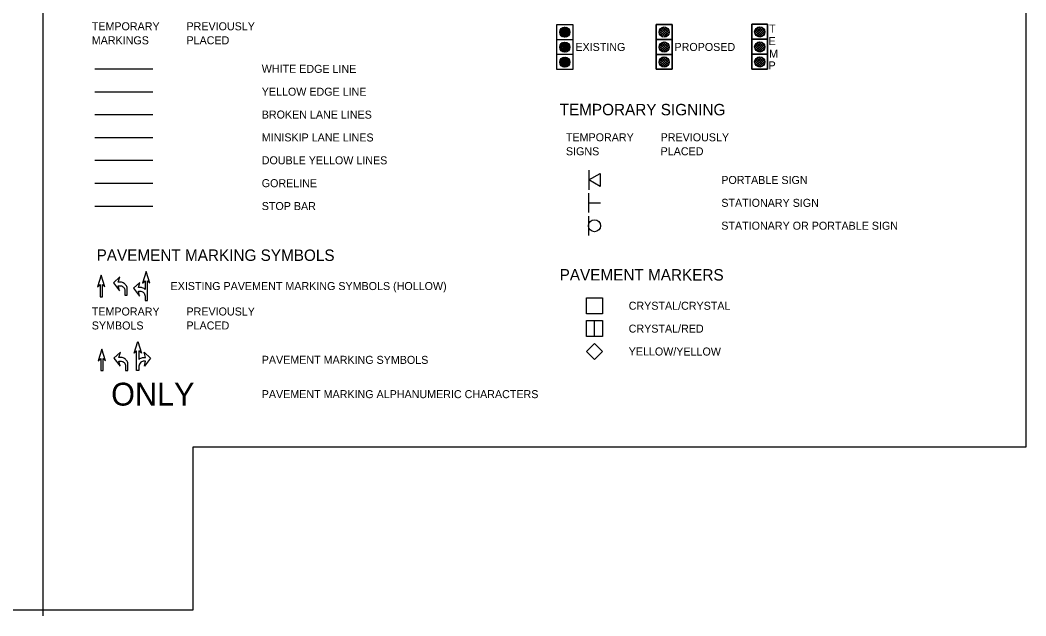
# Model space of a CAD drawing. Extents: x 2486454 to 2490507, y 369321 to 372999.
# Drawn here: x 2487627 to 2488507, y 370213 to 370734 of the extents above; entities that cross this region are included whole.
import ezdxf

# ---------------------------------------------------------------- set-up
doc = ezdxf.new("R2010")
doc.units = 0
for name, color, linetype in [('Exist Mkg Solid White Crosswalks', 7, 'Continuous'), ('MARK CRYSTAL CRYSTAL RPM CELL', 7, 'Continuous'), ('MARK CRYSTAL RED RPM CELL', 7, 'Continuous'), ('MARK YELLOW RPM CELL', 7, 'Continuous'), ('TC DEV SIGN', 7, 'Continuous'), ('TC DEV SIGNAL', 7, 'Continuous'), ('TC PM CENTER DOUBLE 6 Y', 7, 'Continuous'), ('TC PM CHARACTER', 7, 'Continuous'), ('TC PM EDGELINE 6 W P6', 7, 'Continuous'), ('TC PM EDGELINE 6 Y P7', 7, 'Continuous'), ('TC PM GORELINE 12 W PS', 7, 'Continuous'), ('TC PM MINISKIP 3-9 6 W PK', 7, 'Continuous'), ('TC PM SKIP 6 W PJ', 7, 'Continuous'), ('TC PM STOP BAR 24 W P2', 7, 'Continuous'), ('TC PM SYMBOL', 7, 'Continuous'), ('TC SHEET BORDER LINE THIN', 7, 'Continuous'), ('TC SHEET LAYOUT SHAPE', 7, 'Continuous'), ('TC SHEET TEXT', 7, 'Continuous')]:
    doc.layers.add(name, color=color, linetype=linetype)

msp = doc.modelspace()

# ---------------------------------------------------------------- linework, layer by layer
at = {"layer": 'Exist Mkg Solid White Crosswalks'}
for points in [[(2487695.06, 370500.97), (2487697.23, 370502.97), (2487697.23, 370492.3), (2487699.23, 370492.3), (2487699.23, 370502.97), (2487701.39, 370500.97), (2487698.22, 370511.13)], [(2487718.95, 370493.72), (2487720.95, 370493.72), (2487720.94, 370498.88), (2487720.89, 370499.84), (2487720.76, 370500.56), (2487720.51, 370501.35), (2487720.16, 370502.01), (2487719.82, 370502.52), (2487719.25, 370503.18), (2487718.75, 370503.62), (2487718.15, 370504.09), (2487717.36, 370504.56), (2487716.73, 370504.81), (2487715.88, 370505.06), (2487714.71, 370505.22), (2487713.11, 370505.22), (2487714.44, 370509.71), (2487708.77, 370504.54), (2487714.11, 370497.55), (2487713.11, 370502.05), (2487714.44, 370502.05), (2487715.19, 370502.01), (2487715.88, 370501.82), (2487716.42, 370501.57), (2487717.11, 370501.16), (2487717.58, 370500.78), (2487718.12, 370500.12), (2487718.5, 370499.37), (2487718.78, 370498.61), (2487718.94, 370497.55)], [(2487738.59, 370488.97), (2487738.58, 370506.3), (2487740.74, 370504.3), (2487737.57, 370514.47), (2487734.41, 370504.3), (2487736.58, 370506.3), (2487736.58, 370498.76), (2487735.66, 370499.48), (2487734.96, 370499.9), (2487734.06, 370500.22), (2487733.33, 370500.38), (2487732.4, 370500.51), (2487730.75, 370500.46), (2487732.08, 370504.96), (2487726.41, 370499.79), (2487731.75, 370492.8), (2487730.75, 370497.3), (2487732.05, 370497.27), (2487732.81, 370497.24), (2487733.58, 370497.05), (2487734.26, 370496.7), (2487734.93, 370496.31), (2487735.6, 370495.61), (2487736.12, 370494.74), (2487736.44, 370493.82), (2487736.6, 370492.76), (2487736.59, 370488.97)]]:
    msp.add_lwpolyline(points, close=True, dxfattribs=at)
at = {"layer": 'MARK CRYSTAL CRYSTAL RPM CELL'}
msp.add_lwpolyline([(2488122.41, 370491.49), (2488136.41, 370491.48), (2488136.41, 370477.49), (2488122.41, 370477.49), (2488122.41, 370491.49)], dxfattribs=at)
at = {"layer": 'MARK CRYSTAL RED RPM CELL'}
msp.add_lwpolyline([(2488122.41, 370471.49), (2488136.41, 370471.48), (2488136.41, 370457.49), (2488122.41, 370457.49), (2488122.41, 370471.49)], dxfattribs=at)
for points in [[(2488129.41, 370471.49), (2488136.41, 370471.48), (2488136.41, 370457.49), (2488129.4, 370457.49)], [(2488129.41, 370437.49), (2488136.41, 370444.48), (2488129.41, 370451.48), (2488122.41, 370444.48)]]:
    msp.add_lwpolyline(points, close=True, dxfattribs=at)
at = {"layer": 'MARK YELLOW RPM CELL'}
msp.add_lwpolyline([(2488129.41, 370437.49), (2488136.41, 370444.48), (2488129.41, 370451.48), (2488122.41, 370444.48)], close=True, dxfattribs=at)
at = {"layer": 'TC DEV SIGN'}
for p, q in [((2488124.51, 370602.98), (2488124.51, 370586)), ((2488124.51, 370594.49), (2488134.31, 370600.11)), ((2488134.31, 370588.86), (2488124.51, 370594.49)), ((2488134.31, 370600.11), (2488134.31, 370588.86)), ((2488124.15, 370582.98), (2488124.15, 370566)), ((2488124.15, 370574.49), (2488134.67, 370574.49)), ((2488124.15, 370562.98), (2488124.15, 370546))]:
    msp.add_line(p, q, dxfattribs=at)
msp.add_circle((2488129.41, 370554.49), 5.26, dxfattribs=at)
at = {"layer": 'TC DEV SIGNAL'}
for p, q in [((2488096.55, 370730.38), (2488110.35, 370730.38)), ((2488096.55, 370717.28), (2488096.55, 370730.38)), ((2488099.03, 370724), (2488103.14, 370728.11)), ((2488099.13, 370722.69), (2488104.45, 370728.01)), ((2488099.51, 370721.65), (2488105.48, 370727.63)), ((2488099.77, 370726.16), (2488100.98, 370727.37)), ((2488100.07, 370720.81), (2488106.33, 370727.06)), ((2488100.13, 370726.63), (2488106.4, 370720.36)), ((2488100.81, 370720.12), (2488107.01, 370726.33)), ((2488100.88, 370727.3), (2488107.07, 370721.11)), ((2488101.79, 370727.8), (2488107.57, 370722.02)), ((2488102.92, 370728.09), (2488107.86, 370723.15)), ((2488104.4, 370728.02), (2488107.79, 370724.63)), ((2488110.35, 370730.38), (2488110.35, 370717.28)), ((2488185.92, 370723.96), (2488190.22, 370728.26)), ((2488186.27, 370722.16), (2488192.02, 370727.96)), ((2488192.92, 370720.31), (2488186.77, 370726.41)), ((2488187.07, 370720.86), (2488193.32, 370727.11)), ((2488193.97, 370721.36), (2488187.82, 370727.51)), ((2488194.62, 370722.81), (2488189.27, 370728.16)), ((2488194.57, 370724.96), (2488191.47, 370728.11)), ((2488269.49, 370724.02), (2488273.79, 370728.32)), ((2488269.84, 370722.22), (2488275.59, 370728.02)), ((2488276.49, 370720.37), (2488270.34, 370726.47)), ((2488270.64, 370720.92), (2488276.89, 370727.17)), ((2488277.54, 370721.42), (2488271.39, 370727.57)), ((2488278.19, 370722.87), (2488272.84, 370728.22)), ((2488278.14, 370725.02), (2488275.04, 370728.17)), ((2488099.02, 370723.5), (2488103.27, 370719.25)), ((2488099.15, 370724.78), (2488104.55, 370719.38)), ((2488099.55, 370725.8), (2488105.57, 370719.78)), ((2488099.57, 370721.53), (2488101.3, 370719.8)), ((2488101.7, 370719.61), (2488107.53, 370725.43)), ((2488102.81, 370719.29), (2488107.84, 370724.33)), ((2488104.24, 370719.32), (2488107.82, 370722.89)), ((2488189.42, 370719.51), (2488186.02, 370722.96)), ((2488191.47, 370719.61), (2488186.07, 370725.01)), ((2488188.27, 370719.96), (2488194.22, 370725.86)), ((2488189.92, 370719.51), (2488194.72, 370724.26)), ((2488192.82, 370720.26), (2488194.07, 370721.51)), ((2488272.99, 370719.57), (2488269.59, 370723.02)), ((2488275.04, 370719.67), (2488269.64, 370725.07)), ((2488271.84, 370720.02), (2488277.79, 370725.92)), ((2488273.49, 370719.57), (2488278.29, 370724.32)), ((2488276.39, 370720.32), (2488277.64, 370721.57)), ((2488096.55, 370717.28), (2488110.35, 370717.28)), ((2488096.55, 370704.18), (2488096.55, 370717.28)), ((2488099.02, 370710.63), (2488103.41, 370715.02)), ((2488099.02, 370710.72), (2488103.59, 370706.15)), ((2488099.18, 370709.38), (2488104.66, 370714.85)), ((2488099.22, 370711.93), (2488104.8, 370706.36)), ((2488099.3, 370709.03), (2488101.9, 370706.43)), ((2488099.43, 370712.45), (2488101.58, 370714.61)), ((2488099.6, 370708.38), (2488105.65, 370714.44)), ((2488099.67, 370712.9), (2488105.77, 370706.8)), ((2488100.2, 370707.57), (2488106.47, 370713.84)), ((2488100.29, 370713.7), (2488106.56, 370707.42)), ((2488100.96, 370706.91), (2488107.12, 370713.08)), ((2488101.07, 370714.33), (2488107.2, 370708.2)), ((2488101.89, 370706.43), (2488107.61, 370712.15)), ((2488102.03, 370714.79), (2488107.65, 370709.16)), ((2488103.04, 370706.17), (2488107.87, 370711)), ((2488103.21, 370715.02), (2488107.88, 370710.34)), ((2488104.58, 370706.29), (2488107.74, 370709.46)), ((2488104.84, 370714.8), (2488107.67, 370711.97)), ((2488110.35, 370717.28), (2488110.35, 370704.18)), ((2488185.92, 370710.86), (2488190.22, 370715.16)), ((2488189.42, 370706.41), (2488186.02, 370709.86)), ((2488191.47, 370706.51), (2488186.07, 370711.91)), ((2488186.27, 370709.06), (2488192.02, 370714.86)), ((2488192.92, 370707.21), (2488186.77, 370713.31)), ((2488187.07, 370707.76), (2488193.32, 370714.01)), ((2488193.97, 370708.26), (2488187.82, 370714.41)), ((2488188.27, 370706.86), (2488194.22, 370712.76)), ((2488194.62, 370709.71), (2488189.27, 370715.06)), ((2488189.92, 370706.41), (2488194.72, 370711.16)), ((2488194.57, 370711.86), (2488191.47, 370715.01)), ((2488269.49, 370710.92), (2488273.79, 370715.22)), ((2488272.99, 370706.47), (2488269.59, 370709.92)), ((2488275.04, 370706.57), (2488269.64, 370711.97)), ((2488269.84, 370709.12), (2488275.59, 370714.92)), ((2488276.49, 370707.27), (2488270.34, 370713.37)), ((2488270.64, 370707.82), (2488276.89, 370714.07)), ((2488277.54, 370708.32), (2488271.39, 370714.47)), ((2488271.84, 370706.92), (2488277.79, 370712.82)), ((2488278.19, 370709.77), (2488272.84, 370715.12)), ((2488273.49, 370706.47), (2488278.29, 370711.22)), ((2488278.14, 370711.92), (2488275.04, 370715.07)), ((2488110.35, 370704.18), (2488096.55, 370704.18)), ((2488096.55, 370691.08), (2488096.55, 370704.18)), ((2488099.04, 370697.99), (2488102.95, 370701.89)), ((2488099.1, 370696.63), (2488104.31, 370701.84)), ((2488099.45, 370695.57), (2488105.37, 370701.49)), ((2488099.75, 370699.93), (2488105.9, 370693.78)), ((2488100, 370694.7), (2488106.24, 370700.94)), ((2488100.39, 370700.7), (2488106.67, 370694.43)), ((2488100.71, 370694), (2488106.94, 370700.23)), ((2488101.2, 370701.31), (2488107.28, 370695.23)), ((2488102.19, 370701.74), (2488107.71, 370696.22)), ((2488103.41, 370701.92), (2488107.89, 370697.45)), ((2488105.18, 370701.57), (2488107.54, 370699.21)), ((2488110.35, 370704.18), (2488110.35, 370691.08)), ((2488185.92, 370697.76), (2488190.22, 370702.06)), ((2488186.27, 370695.96), (2488192.02, 370701.76)), ((2488192.92, 370694.11), (2488186.77, 370700.21)), ((2488187.07, 370694.66), (2488193.32, 370700.91)), ((2488193.97, 370695.16), (2488187.82, 370701.31)), ((2488194.62, 370696.61), (2488189.27, 370701.96)), ((2488194.57, 370698.76), (2488191.47, 370701.91)), ((2488192.82, 370707.16), (2488194.07, 370708.41)), ((2488269.49, 370697.82), (2488273.79, 370702.12)), ((2488269.84, 370696.02), (2488275.59, 370701.82)), ((2488276.49, 370694.17), (2488270.34, 370700.27)), ((2488270.64, 370694.72), (2488276.89, 370700.97)), ((2488277.54, 370695.22), (2488271.39, 370701.37)), ((2488278.19, 370696.67), (2488272.84, 370702.02)), ((2488278.14, 370698.82), (2488275.04, 370701.97)), ((2488276.39, 370707.22), (2488277.64, 370708.47)), ((2488099.03, 370697.82), (2488103.79, 370693.06)), ((2488099.19, 370696.25), (2488102.21, 370693.22)), ((2488099.28, 370698.99), (2488104.96, 370693.31)), ((2488101.59, 370693.46), (2488107.48, 370699.35)), ((2488102.66, 370693.12), (2488107.82, 370698.28)), ((2488104.04, 370693.09), (2488107.85, 370696.89)), ((2488189.42, 370693.31), (2488186.02, 370696.76)), ((2488191.47, 370693.41), (2488186.07, 370698.81)), ((2488188.27, 370693.76), (2488194.22, 370699.66)), ((2488189.92, 370693.31), (2488194.72, 370698.06)), ((2488192.82, 370694.06), (2488194.07, 370695.31)), ((2488272.99, 370693.37), (2488269.59, 370696.82)), ((2488275.04, 370693.47), (2488269.64, 370698.87)), ((2488271.84, 370693.82), (2488277.79, 370699.72)), ((2488273.49, 370693.37), (2488278.29, 370698.12)), ((2488276.39, 370694.12), (2488277.64, 370695.37)), ((2488110.35, 370691.08), (2488096.55, 370691.08))]:
    msp.add_line(p, q, dxfattribs=at)
for points in [[(2488183.42, 370730.56), (2488197.22, 370730.56), (2488197.22, 370691.26), (2488183.42, 370691.26)], [(2488183.42, 370717.46), (2488197.22, 370717.46), (2488197.22, 370730.56), (2488183.42, 370730.56)], [(2488266.99, 370730.62), (2488280.79, 370730.62), (2488280.79, 370691.32), (2488266.99, 370691.32)], [(2488266.99, 370717.52), (2488280.79, 370717.52), (2488280.79, 370730.62), (2488266.99, 370730.62)], [(2488266.99, 370704.42), (2488280.79, 370704.42), (2488280.79, 370717.52), (2488266.99, 370717.52)], [(2488183.42, 370704.36), (2488197.22, 370704.36), (2488197.22, 370717.46), (2488183.42, 370717.46)], [(2488183.42, 370691.26), (2488197.22, 370691.26), (2488197.22, 370704.36), (2488183.42, 370704.36)], [(2488266.99, 370691.32), (2488280.79, 370691.32), (2488280.79, 370704.42), (2488266.99, 370704.42)]]:
    msp.add_lwpolyline(points, close=True, dxfattribs=at)
for centre in [(2488103.45, 370723.68), (2488190.32, 370723.86), (2488273.89, 370723.92), (2488103.45, 370710.58), (2488190.32, 370710.76), (2488273.89, 370710.82), (2488103.45, 370697.48), (2488190.32, 370697.66), (2488273.89, 370697.72)]:
    msp.add_circle(centre, 4.44, dxfattribs=at)
at = {"layer": 'TC PM CENTER DOUBLE 6 Y'}
msp.add_line((2487692.58, 370611.67), (2487743.22, 370611.67), dxfattribs=at)
at = {"layer": 'TC PM EDGELINE 6 W P6'}
msp.add_line((2487692.58, 370691.67), (2487743.22, 370691.67), dxfattribs=at)
at = {"layer": 'TC PM EDGELINE 6 Y P7'}
msp.add_line((2487692.58, 370671.67), (2487743.22, 370671.67), dxfattribs=at)
at = {"layer": 'TC PM GORELINE 12 W PS'}
msp.add_line((2487692.58, 370591.67), (2487743.22, 370591.67), dxfattribs=at)
at = {"layer": 'TC PM MINISKIP 3-9 6 W PK'}
msp.add_line((2487692.58, 370631.67), (2487743.22, 370631.67), dxfattribs=at)
at = {"layer": 'TC PM SKIP 6 W PJ'}
msp.add_line((2487692.58, 370651.67), (2487743.22, 370651.67), dxfattribs=at)
at = {"layer": 'TC PM STOP BAR 24 W P2'}
msp.add_line((2487692.58, 370571.67), (2487743.22, 370571.67), dxfattribs=at)
at = {"layer": 'TC PM SYMBOL'}
for points in [[(2487695.63, 370436.44), (2487697.8, 370438.44), (2487697.8, 370427.78), (2487699.8, 370427.78), (2487699.8, 370438.44), (2487701.97, 370436.44), (2487698.8, 370446.61)], [(2487695.63, 370436.44), (2487697.8, 370438.44), (2487697.8, 370427.78), (2487699.8, 370427.78), (2487699.8, 370438.44), (2487701.97, 370436.44), (2487698.8, 370446.61)], [(2487729.15, 370427.78), (2487729.15, 370445.11), (2487726.99, 370443.11), (2487730.15, 370453.28), (2487733.32, 370443.11), (2487731.15, 370445.11), (2487731.15, 370437.57), (2487732.07, 370438.3), (2487732.77, 370438.71), (2487733.67, 370439.03), (2487734.41, 370439.19), (2487735.34, 370439.32), (2487736.99, 370439.28), (2487735.65, 370443.78), (2487741.32, 370438.61), (2487735.99, 370431.61), (2487736.99, 370436.11), (2487735.69, 370436.09), (2487734.92, 370436.05), (2487734.15, 370435.86), (2487733.48, 370435.51), (2487732.8, 370435.12), (2487732.13, 370434.42), (2487731.62, 370433.55), (2487731.3, 370432.63), (2487731.14, 370431.57), (2487731.15, 370427.78)], [(2487729.15, 370427.78), (2487729.15, 370445.11), (2487726.99, 370443.11), (2487730.15, 370453.28), (2487733.32, 370443.11), (2487731.15, 370445.11), (2487731.15, 370437.57), (2487732.07, 370438.3), (2487732.77, 370438.71), (2487733.67, 370439.03), (2487734.41, 370439.19), (2487735.34, 370439.32), (2487736.99, 370439.28), (2487735.65, 370443.78), (2487741.32, 370438.61), (2487735.99, 370431.61), (2487736.99, 370436.11), (2487735.69, 370436.09), (2487734.92, 370436.05), (2487734.15, 370435.86), (2487733.48, 370435.51), (2487732.8, 370435.12), (2487732.13, 370434.42), (2487731.62, 370433.55), (2487731.3, 370432.63), (2487731.14, 370431.57), (2487731.15, 370427.78)], [(2487719.52, 370427.78), (2487721.52, 370427.78), (2487721.52, 370432.94), (2487721.46, 370433.9), (2487721.34, 370434.62), (2487721.09, 370435.41), (2487720.74, 370436.07), (2487720.39, 370436.58), (2487719.83, 370437.24), (2487719.32, 370437.68), (2487718.72, 370438.15), (2487717.94, 370438.62), (2487717.31, 370438.87), (2487716.46, 370439.13), (2487715.29, 370439.28), (2487713.68, 370439.28), (2487715.02, 370443.78), (2487709.35, 370438.61), (2487714.68, 370431.61), (2487713.68, 370436.11), (2487715.02, 370436.11), (2487715.76, 370436.07), (2487716.46, 370435.88), (2487716.99, 370435.63), (2487717.68, 370435.22), (2487718.16, 370434.84), (2487718.69, 370434.18), (2487719.07, 370433.43), (2487719.35, 370432.67), (2487719.52, 370431.61)], [(2487719.51, 370427.78), (2487721.51, 370427.78), (2487721.51, 370432.94), (2487721.46, 370433.9), (2487721.34, 370434.62), (2487721.08, 370435.41), (2487720.74, 370436.07), (2487720.39, 370436.57), (2487719.82, 370437.23), (2487719.32, 370437.68), (2487718.72, 370438.15), (2487717.93, 370438.62), (2487717.31, 370438.87), (2487716.45, 370439.12), (2487715.29, 370439.28), (2487713.68, 370439.28), (2487715.01, 370443.78), (2487709.35, 370438.61), (2487714.68, 370431.61), (2487713.68, 370436.11), (2487715.01, 370436.11), (2487715.76, 370436.07), (2487716.45, 370435.88), (2487716.99, 370435.63), (2487717.68, 370435.22), (2487718.16, 370434.84), (2487718.69, 370434.18), (2487719.07, 370433.42), (2487719.35, 370432.67), (2487719.51, 370431.61)]]:
    msp.add_lwpolyline(points, close=True, dxfattribs=at)
at = {"layer": 'TC SHEET BORDER LINE THIN'}
msp.add_line((2487647.27, 371263.19), (2487647.27, 370213.27), dxfattribs=at)
at = {"layer": 'TC SHEET LAYOUT SHAPE'}
msp.add_lwpolyline([(2487016.56, 370666.84), (2487016.56, 370976.16), (2487016.56, 371248.27), (2487026.56, 371258.27), (2487469.58, 371258.27), (2487940.56, 371258.27), (2488261.56, 371258.27), (2488261.56, 371178.27), (2488346.56, 371178.27), (2488346.56, 371226.27), (2488506.56, 371226.27), (2488506.56, 370891.3), (2488506.56, 370612.1), (2488506.56, 370360.77), (2487778.38, 370360.77), (2487778.38, 370218.27), (2487608.92, 370218.27), (2487256.14, 370218.27), (2487016.56, 370218.27)], close=True, dxfattribs=at)

# ---------------------------------------------------------------- texts
at = {"layer": 'TC DEV SIGNAL'}
for s, p in [('T', (2488282.04, 370723.45)), ('E', (2488281.56, 370712.4)), ('M', (2488282.11, 370701.35)), ('P', (2488281.63, 370691.18))]:
    msp.add_text(s, height=7, rotation=359.99986, dxfattribs=at).set_placement(p)
at = {"layer": 'TC PM CHARACTER'}
msp.add_text('ONLY', height=20, rotation=359.99986, dxfattribs=at).set_placement((2487706.86, 370397.19))
at = {"layer": 'TC SHEET TEXT'}
for s, height, rotation, p in [('TEMPORARY', 7, 359.95966, (2487689.92, 370725.41)), ('PREVIOUSLY', 7, 359.95966, (2487772.71, 370725.41)), ('MARKINGS', 7, 359.95966, (2487689.91, 370713.16)), ('PLACED', 7, 359.95966, (2487772.7, 370713.16)), ('EXISTING', 7, 359.95966, (2488112.71, 370707.34)), ('PROPOSED', 7, 359.95966, (2488199.36, 370707.34)), ('WHITE EDGE LINE', 7, 359.95966, (2487838.52, 370688.21)), ('YELLOW EDGE LINE', 7, 359.95966, (2487838.52, 370668.21)), ('TEMPORARY SIGNING', 10, 359.95966, (2488098.93, 370651.11)), ('BROKEN LANE LINES', 7, 359.95966, (2487838.52, 370648.21)), ('MINISKIP LANE LINES', 7, 359.95966, (2487838.52, 370628.22)), ('TEMPORARY', 7, 359.95966, (2488104.45, 370628.34)), ('PREVIOUSLY', 7, 359.95966, (2488187.24, 370628.34)), ('SIGNS', 7, 359.95966, (2488104.44, 370616.09)), ('PLACED', 7, 359.95966, (2488187.23, 370616.09)), ('DOUBLE YELLOW LINES', 7, 359.95966, (2487838.52, 370608.22)), ('GORELINE', 7, 359.95966, (2487838.52, 370588.19)), ('PORTABLE SIGN', 7, 359.95966, (2488240.29, 370591.01)), ('STATIONARY SIGN', 7, 359.95966, (2488240.29, 370571.02)), ('STOP BAR', 7, 359.95966, (2487838.52, 370568.19)), ('STATIONARY OR PORTABLE SIGN', 7, 359.95966, (2488240.29, 370551.05)), ('PAVEMENT MARKING SYMBOLS', 10, 359.95966, (2487694.13, 370523.81)), ('PAVEMENT MARKERS', 10, 359.95966, (2488098.93, 370506.64)), ('EXISTING PAVEMENT MARKING SYMBOLS (HOLLOW)', 7, 0.00008, (2487758.81, 370498.22)), ('TEMPORARY', 7, 359.95966, (2487689.92, 370476)), ('PREVIOUSLY', 7, 359.95966, (2487772.71, 370476)), ('CRYSTAL/CRYSTAL', 7, 359.95966, (2488159.32, 370481.02)), ('SYMBOLS', 7, 359.95966, (2487689.91, 370463.75)), ('PLACED', 7, 359.95966, (2487772.7, 370463.75)), ('CRYSTAL/RED', 7, 359.95966, (2488159.32, 370461.01)), ('YELLOW/YELLOW', 7, 359.95966, (2488159.32, 370441.01)), ('PAVEMENT MARKING SYMBOLS', 7, 359.95966, (2487838.52, 370433.75)), ('PAVEMENT MARKING ALPHANUMERIC CHARACTERS', 7, 0.00008, (2487838.52, 370403.69))]:
    msp.add_text(s, height=height, rotation=rotation, dxfattribs=at).set_placement(p)

doc.saveas('drawing.dxf')
